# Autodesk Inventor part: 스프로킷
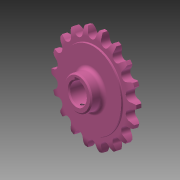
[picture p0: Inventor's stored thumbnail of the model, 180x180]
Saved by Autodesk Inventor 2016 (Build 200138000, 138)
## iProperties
Created: 2016-03
Part Number: 스프로킷
Material: 강철, 탄소
Document SubType Name: Modeling
Designer: mduedu
Density: 7.87 g/cm^3
Mass: 301.818 g
Surface Area: 124.882 cm^2
Volume: 38.3505 cm^3
Appearance: 분홍색
Author: mduedu
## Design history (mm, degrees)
sketch "스케치1"
  geometry: L1 (0, 5)-(29.5, 5); L2 (29.5, 5)-(29.5, 4.1); L3 (30, 3.6)-(33.625, 3.6); L4 (40, 2)-(40, 0); L5 (40, 0)-(0, 0); L6 (0, 0)-(0, 5); L7 (0, -5)-(29.5, -5); L8 (29.5, -5)-(29.5, -4.1); L9 (30, -3.6)-(33.625, -3.6); L10 (40, -2)-(40, 0); L11 (0, 0)-(0, -5); A1 r 13.5 centre (33.625, -9.9) between (40, 2) and (33.625, 3.6); A2 r 13.5 centre (33.625, 9.9) between (33.625, -3.6) and (40, -2); A3 r 0.5 centre (30, 4.1) between (29.5, 4.1) and (30, 3.6); A4 r 0.5 centre (30, -4.1) between (30, -3.6) and (29.5, -4.1); 2 further points
  constraints: 22 end point, 8 point on circle, 6 symmetric about line, 5 tangent, 4 centre point, 4 parallel, 4 point on line, 1 equal radius, 1 horizontal, 1 perpendicular, 1 other
  dimensions: "d0" = 80 diameter of L4 L6; "d2" = 59 diameter of L2 L6; "d3" = 1.6 vertical distance of L4.start L3.end; "d4" = 3.6 distance from line of L4.end L3; "d5" = 5 distance between parallel lines of L5 L1; "d6" = 13.5 radius of A1; "d15" = 0.5 radius of A3
revolve "회전1" sketch "스케치1" stored, may be unused: angle "d7" = 90 deg
sketch "스케치2" dims "d8" = 65.2, "d11" = 80
  geometry: L1 (0, 0)-(0, 32.6); A1 r 36.57 centre (0, 0) between (-16.231, 32.771) and (0, 36.57); A2 r 3.97 centre (0, 36.57) between (-3.866, 35.665) and (0, 32.6); A3 r 12.7 centre (-16.231, 32.771) between (-3.866, 35.665) and (-5.534, 39.615); A4 r 12.7 centre (16.231, 32.771) between (5.534, 39.615) and (3.866, 35.665); A5 r 3.97 centre (0, 36.57) between (0, 32.6) and (3.866, 35.665); A6 r 40 centre (0, 0) between (5.534, 39.615) and (-5.534, 39.615); 2 further points
  constraints: 12 point on circle, 6 centre point, 4 coincident, 3 symmetric about line, 2 end point, 1 point on line, 1 tangent, 1 vertical, 1 vertical alignment, 7 other
  dimensions: "d10" = 73.14 diameter of A1; "d12" = 12.7 radius of A3
extrude "돌출1" cut sketch "스케치2" stored distance "d13" = 10; taper "d14" = 0 deg
sketch "스케치3"
  geometry: C1 r 13 at (0, 0); 1 further point
  constraints: 1 centre point, 1 coincident
  dimensions: "d19" = 26 diameter of C1
extrude "돌출2" join sketch "스케치3" distance "d20" = 10; taper "d21" = 0 deg
fillet "모깎기1" dims "d22" = 3
sketch "스케치4"
  geometry: L1 (-2.5, 0)-(2.5, 0); L2 (2.5, 0)-(2.5, 10.3); L3 (2.5, 10.3)-(-2.5, 10.3); L4 (-2.5, 10.3)-(-2.5, 0); C1 r 8 at (0, 0); 2 further points
  constraints: 8 end point, 2 coincident, 2 parallel, 1 centre point, 1 horizontal, 1 midpoint, 1 perpendicular
  dimensions: "d23" = 16 diameter of C1; "d25" = 5 distance of L2.end L3.end; "d26" = 10.3 distance of L1.end L2.end
extrude "돌출3" cut sketch "스케치4" stored distance "d27" = 8; taper "d28" = 0 deg
chamfer "모따기2" distance "d42" = 1; stored, may be unused: second distance "d43" = 2, angle "d44" = 45 deg
node "작업 평면2"
sketch "스케치6"
  geometry: L1 (-12, 15)-(12, 15) reference; 2 further points
  constraints: 1 vertical alignment
  dimensions: "d59" = 4 distance from line of point (0.008, 11) L1
hole "구멍2" sketch "스케치6" at (0.008, 11) diameter "d48" = 3; stored, may be unused: countersink angle "d52" = 90 deg, drill point angle "d54" = 118 deg; dims "d49" = 6, "d50" = 4, "d51" = 2, "d53" = 8
thread "Thread1" dims "d56" = 10, "d57" = 0
node "솔리드1"
pattern_circular "원형 패턴1" dims angle "d17" = 360 deg
other parameters: "d55" = -13
